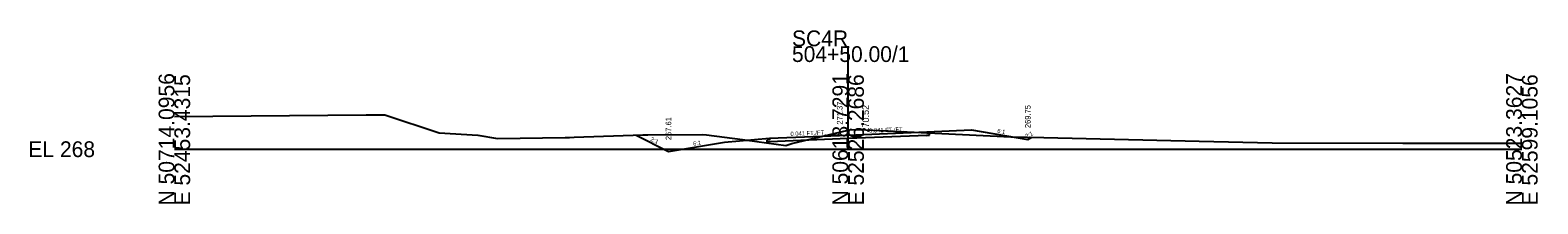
# Model space of a CAD drawing. Extents: x 9740 to 17409, y 8856 to 28416.
# Drawn here: x 9740.2 to 10008.7, y 25361.7 to 25392.5 of the extents above; entities that cross this region are included whole.
import ezdxf

# ---------------------------------------------------------------- set-up
doc = ezdxf.new("R2010")
doc.units = 0
for name, color, linetype in [('Level 10', 7, 'Continuous'), ('Level 11', 7, 'Continuous'), ('Level 12', 7, 'Continuous'), ('Level 32', 7, 'Continuous'), ('Level 33', 7, 'Continuous'), ('Level 59', 7, 'Continuous'), ('Level 6', 7, 'Continuous'), ('Level 60', 7, 'Continuous'), ('Level 63', 7, 'Continuous'), ('Level 7', 7, 'Continuous')]:
    doc.layers.add(name, color=color, linetype=linetype)

msp = doc.modelspace()

# ---------------------------------------------------------------- linework, layer by layer
at = {"layer": 'Level 11'}
for p, q in [((9899.85, 25374.17), (9899.85, 25374.47)), ((9900.35, 25374.19), (9899.85, 25374.17)), ((9899.85, 25373.83), (9900.35, 25373.85)), ((9900.35, 25373.85), (9900.35, 25374.19)), ((9871.85, 25373.03), (9871.35, 25373.01)), ((9871.35, 25373.01), (9871.35, 25372.67)), ((9871.35, 25372.67), (9871.85, 25372.69)), ((9871.85, 25373.33), (9871.85, 25373.03))]:
    msp.add_line(p, q, dxfattribs=at)
at = {"layer": 'Level 12'}
for p, q in [((9899.85, 25373.83), (9885.85, 25373.26)), ((9885.85, 25373.26), (9871.85, 25372.69))]:
    msp.add_line(p, q, dxfattribs=at)
at = {"layer": 'Level 59'}
for p, q in [((9871.85, 25373.33), (9885.85, 25373.9)), ((9885.85, 25373.9), (9899.85, 25374.47))]:
    msp.add_line(p, q, dxfattribs=at)
at = {"layer": 'Level 6'}
for p, q in [((9899.85, 25374.47), (9907.85, 25374.8)), ((9863.85, 25372.66), (9871.85, 25373.33))]:
    msp.add_line(p, q, dxfattribs=at)
at = {"layer": 'Level 60'}
for p, q in [((9765.85, 25377.2), (9799.98, 25377.46)), ((9799.98, 25377.46), (9803.36, 25377.48)), ((9803.36, 25377.48), (9813.02, 25374.28)), ((9813.02, 25374.28), (9819.91, 25373.86)), ((9819.91, 25373.86), (9823.41, 25373.3)), ((9837.05, 25373.51), (9849.27, 25373.92)), ((9849.27, 25373.92), (9850.2, 25373.93)), ((9850.2, 25373.93), (9859.99, 25373.99)), ((9859.99, 25373.99), (9860.6, 25373.92)), ((9860.6, 25373.92), (9867.03, 25373.11)), ((9875.85, 25372.41), (9885.85, 25374.75)), ((9885.85, 25374.75), (9886.53, 25374.91)), ((9886.53, 25374.91), (9889, 25374.84)), ((9889, 25374.84), (9914.83, 25373.57)), ((9914.83, 25373.57), (9920.69, 25373.45)), ((9823.41, 25373.3), (9835.47, 25373.45)), ((9835.47, 25373.45), (9836.2, 25373.48)), ((9836.2, 25373.48), (9837.05, 25373.51)), ((9867.03, 25373.11), (9867.84, 25372.99)), ((9867.84, 25372.99), (9874.73, 25372.06)), ((9874.73, 25372.06), (9875.85, 25372.41)), ((9920.69, 25373.45), (9948.39, 25372.8)), ((9948.39, 25372.8), (9961.39, 25372.5)), ((9961.39, 25372.5), (9984.67, 25372.48)), ((9984.67, 25372.48), (10005.85, 25372.48))]:
    msp.add_line(p, q, dxfattribs=at)
at = {"layer": 'Level 63'}
for p, q in [((9885.85, 25371.38), (9885.85, 25389.68)), ((9765.85, 25371.38), (9885.85, 25371.38)), ((9885.85, 25371.38), (10005.85, 25371.38))]:
    msp.add_line(p, q, dxfattribs=at)
at = {"layer": 'Level 7'}
for p, q in [((9848.07, 25373.88), (9853.85, 25370.99)), ((9907.85, 25374.8), (9917.85, 25373.13)), ((9853.85, 25370.99), (9863.85, 25372.66)), ((9917.85, 25373.13), (9918.57, 25373.5))]:
    msp.add_line(p, q, dxfattribs=at)

# ---------------------------------------------------------------- texts
at = {"layer": 'Level 10'}
msp.add_text('271.37', height=1, rotation=90, dxfattribs=at).set_placement((9884.85, 25375.75))
at = {"layer": 'Level 32'}
for s, rotation, p in [('0.041 FT./FT.', 2.3478, (9875.59, 25373.73)), ('0.041 FT./FT.', 2.3478, (9889.59, 25374.3)), ('6:1', 350.5377, (9912.37, 25374.3)), ('2:1', 26.5651, (9917.59, 25373.29)), ('2:1', 333.435, (9850.57, 25372.92)), ('6:1', 9.4623, (9858.29, 25371.98))]:
    msp.add_text(s, height=0.75, rotation=rotation, dxfattribs=at).set_placement(p)
at = {"layer": 'Level 33'}
for s, p in [('269.75', (9918.35, 25375.13)), ('267.61', (9854.35, 25372.99))]:
    msp.add_text(s, height=1, rotation=90, dxfattribs=at).set_placement(p)
at = {"layer": 'Level 59'}
msp.add_text(' 270.52', height=1.2, rotation=90, dxfattribs=at).set_placement((9889.55, 25373.9))
at = {"layer": 'Level 63'}
for s, p in [('SC4R', (9875.85, 25389.68)), ('504+50.00/1', (9875.85, 25386.88)), ('EL 268', (9739.85, 25369.98))]:
    msp.add_text(s, height=2.8, dxfattribs=at).set_placement(p)
for s, p in [('N 50714.0956', (9765.85, 25361.38)), ('E 52453.4315', (9768.65, 25361.38)), ('N 50618.7291', (9885.85, 25361.38)), ('E 52526.2686', (9888.65, 25361.38)), ('N 50523.3627', (10005.85, 25361.38)), ('E 52599.1056', (10008.65, 25361.38))]:
    msp.add_text(s, height=2.8, rotation=90, dxfattribs=at).set_placement(p)

doc.saveas('drawing.dxf')
